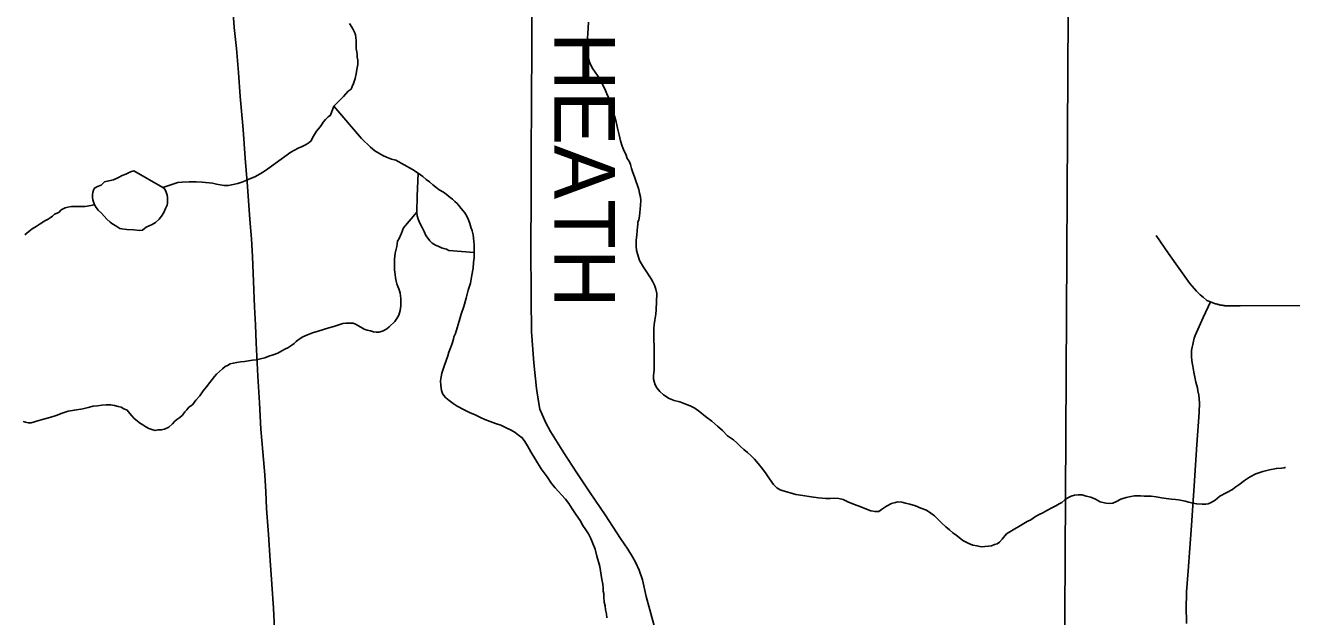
# Model space of a CAD drawing. Extents: x 103424 to 290657, y 38711 to 110967.
# Drawn here: x 114482 to 120775, y 90725 to 93661 of the extents above; entities that cross this region are included whole.
import ezdxf

# ---------------------------------------------------------------- set-up
doc = ezdxf.new("R2010")
doc.units = 0
for name, color, linetype in [('GM_X_Corporation', 7, 'Continuous'), ('GM_X_Minor_Lake', 7, 'Continuous'), ('GM_X_Minor_River', 7, 'Continuous'), ('GM_X_Township_Road', 7, 'Continuous'), ('GM_X_Township_Road_Text', 7, 'Continuous')]:
    doc.layers.add(name, color=color, linetype=linetype)

msp = doc.modelspace()

# ---------------------------------------------------------------- linework, layer by layer
at = {"layer": 'GM_X_Corporation'}
for points in [[(119639, 84504.6), (119641.6, 85722.3), (119634.5, 87732.9), (119633.9, 87813.5), (119633.9, 87824), (119641.1, 89532.2), (119665, 94023.8), (119663.9, 96690), (127752.9, 96778.3), (127904.6, 96781), (127960.9, 96782.1), (128017.2, 96783.1), (128144.7, 96785.8), (131350.5, 96844.5), (131500.4, 96848.9), (132289.6, 96863.9), (132581, 96869.6), (132838, 96874.6), (133225.9, 96882.3), (133496.3, 96888.5), (133864.7, 96896.9), (134160.1, 96903.7)], [(119639, 84504.6), (119641.6, 85722.3), (119634.5, 87732.9), (119633.9, 87813.5), (119633.9, 87824), (119641.1, 89532.2), (119665, 94023.8), (119663.9, 96690), (117026.4, 96688.2), (115542.1, 96665), (105081.7, 96574.5), (103423.7, 96534.8), (103423.7, 70904.9)]]:
    msp.add_lwpolyline(points, dxfattribs=at)
at = {"layer": 'GM_X_Minor_Lake'}
for points in [[(115165, 92856.7), (115020.7, 92938), (115004.6, 92933.9), (114980.5, 92921.5), (114962.4, 92915.2), (114944.3, 92905), (114920.2, 92894.6), (114896, 92888.3), (114875.9, 92884.1), (114857.9, 92867.7), (114839.8, 92861.5), (114825.8, 92853.3), (114819.8, 92843.1), (114817.9, 92831), (114816, 92820.9), (114816.2, 92806.7), (114816.3, 92794.6), (114820.5, 92784.5), (114824.7, 92770.4), (114833, 92756.4), (114843.2, 92744.3), (114859.5, 92728.3), (114873.8, 92714.4), (114886.1, 92698.3), (114902.5, 92684.3)], [(115165, 92856.7), (115020.7, 92938), (115004.6, 92933.9), (114980.5, 92921.5), (114962.4, 92915.2), (114944.3, 92905), (114920.2, 92894.6), (114896, 92888.3), (114875.9, 92884.1), (114857.9, 92867.7), (114839.8, 92861.5), (114825.8, 92853.3), (114819.8, 92843.1), (114817.9, 92831), (114816, 92820.9), (114816.2, 92806.7), (114816.3, 92794.6), (114820.5, 92784.5), (114824.7, 92770.4), (114833, 92756.4), (114843.2, 92744.3), (114859.5, 92728.3), (114873.8, 92714.4), (114886.1, 92698.3), (114902.5, 92684.3), (114916.7, 92674.4), (114930.9, 92666.4), (114941.1, 92658.4), (114951.3, 92652.5), (114961.4, 92650.6), (114985.7, 92646.8), (115020.1, 92645.1), (115048.4, 92643.3), (115064.5, 92643.5), (115082.5, 92659.9), (115112.6, 92672.3), (115128.7, 92682.5), (115146.7, 92698.9), (115158.6, 92713.1), (115170.5, 92731.4), (115178.4, 92751.7), (115186.3, 92768), (115188.1, 92780.1), (115188, 92796.3), (115187.8, 92806.4), (115185.7, 92818.5), (115179.4, 92838.6), (115173.2, 92848.7), (115165, 92856.7)], [(114902.5, 92684.3), (114916.7, 92674.4), (114930.9, 92666.4), (114941.1, 92658.4), (114951.3, 92652.5), (114961.4, 92650.6), (114985.7, 92646.8), (115020.1, 92645.1), (115048.4, 92643.3), (115064.5, 92643.5), (115082.5, 92659.9), (115112.6, 92672.3), (115128.7, 92682.5), (115146.7, 92698.9), (115158.6, 92713.1), (115170.5, 92731.4), (115178.4, 92751.7), (115186.3, 92768), (115188.1, 92780.1), (115188, 92796.3), (115187.8, 92806.4), (115185.7, 92818.5), (115179.4, 92838.6), (115173.2, 92848.7), (115165, 92856.7)]]:
    msp.add_lwpolyline(points, dxfattribs=at)
at = {"layer": 'GM_X_Minor_River'}
for points in [[(115165, 92856.7), (115239.5, 92881.6), (115261.7, 92881.9), (115296, 92884.2), (115330.3, 92884.6), (115360.6, 92882.8), (115411.2, 92877.3), (115431.4, 92873.4), (115449.7, 92869.6), (115469.9, 92865.7), (115492.1, 92866), (115514.3, 92870.2), (115538.4, 92876.5), (115562.6, 92884.8), (115592.7, 92897.3), (115622.9, 92909.7), (115649, 92924.1), (115675, 92940.5), (115699.1, 92956.9), (115723.1, 92975.3), (115801.2, 93030.7), (115819.3, 93040.9), (115837.3, 93051.2), (115857.5, 93059.5), (115877.5, 93069.8), (115891.5, 93080.1), (115901.5, 93088.2), (115909.5, 93102.5), (115919.4, 93118.7), (115929.3, 93135), (115939.2, 93147.2), (115951.2, 93163.5), (115961.1, 93179.7), (115973, 93194), (115987, 93206.3), (115999, 93214.5), (116014.7, 93259.1), (116062.6, 93308), (116086.5, 93334.5), (116100.5, 93344.8), (116106.4, 93357), (116112.3, 93373.2), (116120.1, 93397.5), (116125.9, 93419.8), (116129.7, 93442), (116133.4, 93466.3), (116133.2, 93488.6), (116131, 93502.7), (116130.8, 93516.8), (116128.7, 93528.9), (116126.5, 93545.1), (116126.3, 93563.2), (116126, 93583.4), (116123.8, 93601.6), (116121.6, 93613.7), (116117.4, 93627.8), (116111.2, 93639.9), (116105, 93651.9), (116092.7, 93670)], [(117280.2, 93677.7), (117276.8, 93621.1), (117275.1, 93596.9), (117271.3, 93574.6), (117271.5, 93556.4), (117273.7, 93540.3), (117276, 93520.1), (117280.3, 93495.9), (117288.7, 93469.7), (117301.1, 93445.6), (117336, 93395.4), (117348.4, 93371.3), (117360.8, 93345.2), (117371.2, 93321), (117385.7, 93288.9), (117394.1, 93264.7), (117402.5, 93238.5), (117408.8, 93212.3), (117417.3, 93182.1), (117423.7, 93149.8)], [(116014.7, 93259.1), (116151.9, 93098.8), (116196.8, 93056.8), (116219.2, 93038.9), (116257.9, 93015), (116276.1, 93007.1), (116300.5, 92997.2), (116322.8, 92991.4), (116406.1, 92945.8), (116434.6, 92927.9), (116457, 92909.9), (116473.3, 92895.9), (116489.7, 92884), (116506, 92870), (116522.3, 92858), (116538.6, 92844), (116558.9, 92832.1), (116573.2, 92822.1), (116583.4, 92814.2), (116593.6, 92806.2), (116603.7, 92798.2), (116616, 92786.2), (116628.2, 92776.2), (116636.4, 92766.2), (116646.7, 92752.2), (116656.9, 92740.2), (116665.1, 92730.1), (116675.4, 92714.1), (116683.7, 92696), (116690, 92677.8), (116696.2, 92659.7), (116702.5, 92641.6), (116706.8, 92621.4), (116709, 92605.3), (116711.2, 92587.1), (116711.4, 92571), (116711.6, 92554.8), (116711.9, 92532.6), (116712.2, 92506.3), (116708.4, 92484.1), (116706.7, 92455.8), (116701, 92421.4), (116693.4, 92380.9), (116681.7, 92346.4), (116672.1, 92305.9), (116660.5, 92265.4), (116646.8, 92226.9), (116637.1, 92192.4), (116627.3, 92160), (116619.6, 92131.6), (116611.7, 92115.4), (116609.8, 92103.3), (116602, 92081), (116592.2, 92054.6), (116586.3, 92038.4), (116580.5, 92020.1), (116562.9, 91969.4), (116557.1, 91949.2), (116551.2, 91935), (116547.4, 91916.8), (116545.6, 91896.5), (116545.9, 91872.3), (116550.2, 91848.1), (116554.4, 91834), (116560.6, 91824), (116570.8, 91811.9), (116587.1, 91798), (116607.5, 91784), (116627.8, 91770.1), (116662.4, 91752.2), (116688.8, 91738.4), (116717.2, 91726.5), (116743.6, 91714.7), (116765.9, 91704.8), (116792.3, 91694.9), (116818.7, 91685.1), (116845.1, 91675.3), (116871.4, 91663.4), (116895.8, 91651.5), (116916.2, 91639.6), (116932.5, 91625.6), (116950.8, 91613.7), (116963.1, 91595.6), (116977.5, 91573.5), (116994, 91543.4), (117016.7, 91505.2), (117045.5, 91459), (117074.2, 91418.9), (117096.8, 91386.8), (117115.3, 91364.8), (117131.6, 91346.8), (117146, 91330.7), (117166.4, 91308.7), (117182.8, 91286.6), (117199.3, 91260.5), (117219.8, 91230.5), (117238.3, 91202.4), (117252.8, 91178.3)], [(117423.7, 93149.8), (117432.2, 93117.6), (117438.6, 93087.3), (117446.9, 93061.2), (117457.3, 93037), (117465.6, 93020.9), (117471.9, 93000.8), (117482.1, 92986.8), (117488.4, 92970.6), (117494.7, 92950.5), (117501, 92930.4), (117509.3, 92908.2), (117517.7, 92884.1), (117524, 92865.9), (117530.2, 92845.8), (117534.5, 92827.7), (117538.7, 92809.5), (117541, 92791.3), (117539.2, 92769.1), (117537.4, 92748.9), (117535.6, 92732.7), (117533.8, 92714.5), (117530, 92696.3), (117526.1, 92684.1), (117526.2, 92674), (117524.3, 92659.9), (117522.5, 92641.7), (117520.8, 92619.4), (117517, 92595.1), (117517.4, 92564.8), (117519.6, 92542.6), (117525.9, 92522.5), (117534.3, 92494.3), (117552.9, 92460.1), (117569.4, 92436), (117581.7, 92418), (117592, 92401.9), (117600.2, 92387.9), (117608.5, 92371.8), (117614.8, 92351.6), (117619.1, 92329.5), (117616, 92248.6), (117614.2, 92226.4), (117610.5, 92198.1), (117606.7, 92175.8), (117604.9, 92155.6), (117605.2, 92131.3), (117605.6, 92101), (117606, 92066.7), (117606.4, 92032.3), (117606.8, 91996), (117607.1, 91971.7), (117607.3, 91951.5), (117605.5, 91935.4), (117603.6, 91923.2), (117603.8, 91905), (117606, 91892.9), (117612.2, 91876.8), (117620.5, 91860.7), (117634.8, 91842.7), (117653.2, 91826.7), (117681.7, 91808.8), (117706, 91799), (117734.4, 91791.2), (117758.8, 91781.3), (117785.1, 91771.5), (117809.5, 91759.6), (117833.9, 91741.7), (117862.5, 91719.7), (117893.1, 91695.8), (117921.6, 91671.8), (117946.1, 91649.8), (117970.6, 91623.8), (118001.2, 91603.9), (118017.5, 91587.9), (118035.9, 91569.9), (118052.2, 91555.9), (118070.6, 91539.9), (118086.9, 91526), (118105.3, 91508), (118123.7, 91485.9), (118144.2, 91459.9), (118162.7, 91433.8), (118179.1, 91409.7), (118199.7, 91381.6), (118216, 91365.6), (118232.3, 91355.7), (118242.4, 91351.7), (118311.3, 91332.2), (118345.7, 91326.5), (118386.2, 91320.8), (118422.6, 91315.1), (118459, 91311.5), (118481.2, 91311.7), (118503.4, 91313.9), (118523.6, 91312.1), (118545.9, 91306.3), (118572.3, 91294.4), (118602.7, 91282.6), (118633.2, 91270.8), (118661.6, 91258.9)], [(116434.6, 92927.9), (116429.1, 92812.3)], [(114479.1, 92621.5), (114499.1, 92637.9), (114515.1, 92650.2), (114535.1, 92662.5), (114555.2, 92674.8), (114579.2, 92691.2), (114595.3, 92699.5), (114605.3, 92705.6), (114617.3, 92713.8), (114627.3, 92724), (114639.4, 92728.2), (114649.4, 92734.3), (114659.4, 92744.5), (114679.5, 92754.8), (114693.6, 92759), (114711.7, 92761.2), (114723.8, 92761.3), (114733.9, 92761.5), (114748.1, 92761.6), (114764.2, 92761.7), (114778.4, 92761.9), (114824.7, 92770.4)], [(116429.1, 92812.3), (116426.8, 92733.8), (116429, 92715.7), (116433.2, 92699.5), (116443.6, 92675.4), (116453.9, 92657.3), (116464.2, 92637.2), (116472.6, 92617.1), (116482.8, 92603.1), (116491, 92591), (116503.3, 92579), (116519.6, 92569.1), (116535.8, 92563.2), (116550, 92557.2), (116562.2, 92553.3), (116574.3, 92549.4), (116586.5, 92543.5), (116711.9, 92532.6)], [(116426.8, 92733.8), (116361, 92656.4), (116351.2, 92630), (116339.4, 92603.6), (116331.5, 92589.4), (116327.8, 92563.1), (116320.1, 92530.7), (116316.4, 92500.4), (116316.7, 92474.1), (116317, 92447.8), (116319.3, 92423.6), (116321.5, 92407.5), (116323.7, 92391.3), (116327.9, 92377.3), (116332.1, 92365.2), (116338.3, 92353.1), (116340.4, 92343), (116344.6, 92330.9), (116346.8, 92318.8), (116346.9, 92304.7), (116347.1, 92290.6), (116347.4, 92268.3), (116345.5, 92256.2), (116343.6, 92246.1), (116337.8, 92221.8), (116327.9, 92205.5), (116318, 92191.3), (116290, 92164.7), (116278, 92154.5), (116266, 92148.3), (116255.9, 92142.2), (116237.8, 92137.9), (116225.7, 92137.8), (116211.5, 92139.7), (116197.3, 92143.6), (116181.1, 92147.5), (116164.9, 92153.4), (116148.6, 92163.3), (116122.2, 92177.2), (116110, 92183.1), (116089.8, 92182.9), (116073.7, 92182.8), (116059.6, 92180.6), (116039.4, 92174.4), (116015.3, 92166), (115989.1, 92159.7), (115963, 92151.4), (115936.8, 92143), (115908.6, 92134.7), (115884.5, 92124.3), (115860.4, 92114), (115838.3, 92099.6), (115828.3, 92091.4), (115818.4, 92081.2), (115806.3, 92073), (115786.3, 92060.7), (115774.2, 92054.5), (115756.2, 92044.3), (115736.1, 92034), (115714, 92025.7), (115691.8, 92019.4), (115671.7, 92011.1), (115629.4, 92000.6), (115611.3, 91998.4), (115571, 91991.9), (115550.8, 91989.7), (115532.7, 91987.5), (115514.5, 91983.3), (115500.4, 91981.1), (115486.4, 91972.9), (115474.3, 91966.7), (115462.3, 91956.5), (115432.3, 91929.9), (115422.4, 91917.7), (115410.4, 91903.4), (115398.5, 91887.2), (115382.6, 91866.8), (115364.6, 91846.4), (115348.8, 91822), (115328.8, 91799.6), (115312.9, 91777.2), (115294.9, 91764.9), (115285, 91752.7), (115275, 91742.5), (115263, 91726.2), (115249, 91713.9), (115235, 91703.7), (115225, 91695.5), (115213, 91683.3), (115195.1, 91666.9), (115173, 91656.6), (115156.9, 91652.4), (115140.7, 91652.2), (115126.6, 91650.1), (115110.4, 91654), (115096.2, 91659.9), (115079.9, 91667.8), (115065.7, 91677.8), (115049.4, 91687.7), (115037.2, 91697.7), (115022.9, 91709.7)], [(115022.9, 91709.7), (115010.6, 91721.7), (115000.4, 91733.7), (114988.1, 91749.7), (114971.8, 91757.6), (114957.6, 91765.6), (114943.4, 91769.5), (114925.2, 91773.3), (114905, 91777.2), (114882.7, 91777), (114862.6, 91774.7), (114840.4, 91772.5), (114818.2, 91770.3), (114794, 91764), (114767.8, 91757.6), (114725.5, 91751.1), (114695.3, 91744.8), (114665.1, 91736.4), (114634.9, 91724), (114602.8, 91713.6), (114572.5, 91705.2), (114548.4, 91698.9), (114510.1, 91688.4), (114496, 91688.3), (114481.8, 91690.1), (114471.7, 91694.1)], [(118661.6, 91258.9), (118683.9, 91251.1), (118704.1, 91247.2), (118722.3, 91247.4), (118736.3, 91257.6), (118760.4, 91274), (118786.5, 91286.4), (118806.6, 91292.7), (118816.7, 91294.8), (118836.9, 91293), (118855.1, 91289.1), (118877.4, 91283.3), (118905.8, 91275.5), (118932.2, 91263.6), (118960.6, 91253.8), (118980.9, 91239.9), (118999.3, 91225.9), (119017.6, 91207.9), (119036, 91189.9), (119056.4, 91171.9), (119074.8, 91155.9), (119091.1, 91142), (119107.4, 91130), (119121.7, 91118), (119140, 91104.1), (119170.5, 91088.2), (119190.8, 91080.3), (119211, 91076.5), (119231.3, 91072.7), (119249.5, 91072.8), (119267.6, 91075), (119283.7, 91077.2), (119297.8, 91083.4), (119311.9, 91087.6), (119321.9, 91095.8), (119335.9, 91110), (119357.8, 91136.5), (119460.1, 91198.2), (119478.2, 91206.4), (119490.2, 91214.6), (119502.2, 91222.8), (119520.3, 91233.1), (119538.3, 91241.4), (119560.4, 91253.7), (119582.5, 91266), (119602.6, 91276.3), (119618.6, 91284.6), (119632.7, 91292.8), (119646.7, 91305.1), (119662.7, 91315.3), (119678.8, 91323.6), (119694.9, 91327.8), (119713, 91330), (119733.2, 91330.2), (119753.5, 91324.3), (119775.8, 91318.5), (119800.1, 91308.6), (119822.5, 91294.7), (119850.8, 91288.9), (119867, 91287.1), (119885.2, 91289.2), (119903.3, 91297.5), (119925.4, 91307.8), (119951.5, 91316.2), (119975.7, 91322.5), (119993.8, 91324.7), (120008, 91324.8), (120024.1, 91325), (120042.3, 91323.1), (120076.6, 91323.5), (120100.9, 91319.7), (120127.2, 91315.9), (120151.5, 91312.1), (120177.8, 91308.3), (120198, 91306.5), (120212.2, 91304.6), (120228.4, 91302.8), (120244.6, 91298.9), (120262.8, 91293), (120283.1, 91289.2), (120303.3, 91285.3), (120329.6, 91283.6), (120347.8, 91283.7), (120359.8, 91285.9), (120373.9, 91292.1), (120394, 91304.4), (120418, 91322.8), (120480.2, 91355.8), (120492.2, 91366), (120512.2, 91380.3), (120540.3, 91400.8), (120564.3, 91417.2), (120596.5, 91433.7), (120630.6, 91446.2), (120664.9, 91454.6), (120699.1, 91461), (120723.4, 91463.2), (120737.5, 91463.4), (120741.5, 91465.4), (120743.5, 91465.5)], [(117252.8, 91178.3), (117267.2, 91156.2), (117279.5, 91136.1), (117291.9, 91114), (117302.3, 91087.8), (117312.7, 91059.7), (117321.2, 91025.4), (117329.6, 90997.2), (117335.9, 90975), (117346.8, 90910.5), (117351.1, 90886.3), (117353.3, 90866.1), (117353.5, 90852), (117355.7, 90839.9), (117355.9, 90823.7), (117358.2, 90797.5), (117362.4, 90779.3), (117364.7, 90759.1), (117369, 90739), (117371.2, 90718.8)]]:
    msp.add_lwpolyline(points, dxfattribs=at)
at = {"layer": 'GM_X_Township_Road'}
for points in [[(115720.1, 90665.1), (115714.4, 90767.8), (115706.5, 90885.8), (115698.5, 91003.8), (115689.6, 91132.7), (115680.8, 91261.6), (115676.3, 91345.8), (115671.9, 91429.9), (115662.3, 91543.1), (115652.7, 91656.3), (115644.7, 91787.7), (115636.7, 91919.2), (115629.1, 92084.1), (115625, 92174.1), (115620.8, 92264), (115615.7, 92389), (115610.5, 92514), (115605.7, 92601.3), (115597.9, 92696.7), (115585.2, 92861.3), (115574.3, 93002.4), (115563.5, 93143.5), (115550, 93308), (115540.3, 93427.2), (115530.6, 93546.3), (115519.9, 93650.7), (115511.7, 93769.7)], [(117620.7, 90625.1), (117584.4, 90758.8), (117567.2, 90825.5), (117548.3, 90908.9), (117532.7, 90956.5), (117514.1, 90995.2), (117498.2, 91023.1), (117475.6, 91060.8), (117439, 91112.8), (117363.9, 91230.7), (117288.3, 91340.3), (117222.7, 91439.3), (117157.1, 91538.3), (117091.9, 91643.8), (117068.2, 91687.1), (117049.5, 91729.2), (117039.1, 91756), (117033, 91783.5), (117021.1, 91857.5), (117008.9, 91984.7), (116997.7, 92139.9), (116995.7, 92304.9), (116994.6, 92394), (116993.6, 92483), (116994.5, 92608.1), (116995, 92755), (116995.5, 92901.9), (116996, 93066.9), (116996.4, 93232), (116998.3, 93608.2), (116999.2, 93704.6)], [(120100.4, 92618.4), (120162.5, 92528.7), (120215.8, 92454.2), (120269.1, 92379.8), (120280.9, 92365.9), (120301.2, 92342), (120320.1, 92323.1), (120334.7, 92310.8), (120353.8, 92295.5), (120370.5, 92287.8), (120378.7, 92284.7), (120383, 92283.2), (120387, 92281.7), (120391.3, 92280.3), (120395.3, 92279), (120399.6, 92277.7), (120403.9, 92276.5), (120408.1, 92275.5), (120412.4, 92274.5), (120416.7, 92273.4), (120421, 92272.6), (120425.2, 92271.8), (120429.5, 92271.1), (120433.8, 92270.4), (120438.4, 92269.8), (120442.6, 92269.3), (120446.9, 92268.9), (120518.1, 92267.9), (120854.2, 92270)], [(120251.7, 90690.9), (120250.9, 90779.5), (120251.6, 90830.7), (120252.7, 90847.8), (120259.5, 90953.3), (120268.2, 91065.6), (120277, 91178), (120283.9, 91276.4), (120290.7, 91374.7), (120297.3, 91477.7), (120303.9, 91580.6), (120314.8, 91738.1), (120316.7, 91786.7), (120312.5, 91825.5), (120309.1, 91846.8), (120306.8, 91861.2), (120298.7, 91888.8), (120288.4, 91939.4), (120282.7, 91969.3), (120279.7, 91985.5), (120277.7, 91996.7), (120276.6, 92015.3), (120277.4, 92046.5), (120280.5, 92062.9), (120282.7, 92076), (120286.2, 92093.3), (120290, 92107.5), (120294.9, 92121.6), (120335.2, 92210.1), (120370.5, 92287.8)]]:
    msp.add_lwpolyline(points, dxfattribs=at)

# ---------------------------------------------------------------- texts
at = {"layer": 'GM_X_Township_Road_Text'}
msp.add_text('HEATH', height=301.87, rotation=270, dxfattribs=at).set_placement((117110.1, 93627.8))

doc.saveas('drawing.dxf')
